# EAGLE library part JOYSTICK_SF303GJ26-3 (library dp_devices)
Multi way switch Mfr no: SF303GJ26-3 SF303GJ26-3
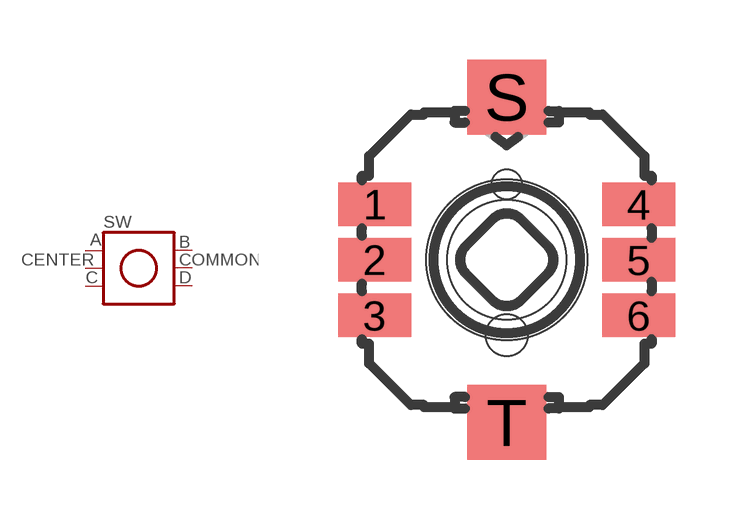
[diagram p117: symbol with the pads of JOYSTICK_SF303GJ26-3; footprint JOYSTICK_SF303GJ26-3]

Designator prefix SW

## JOYSTICK_SF303GJ26-3  [JOYSTICK_SF303GJ26-3]
1  A
2  CENTER
3  C
4  B
5  COMMON
6  D

## Footprint JOYSTICK_SF303GJ26-3 (pad centres in mm)
smd 1.85 x 1.1: 1 -3.325,1.4; 2 -3.325,0; 3 -3.325,-1.4; 4 3.325,1.4; 5 3.325,0; 6 3.325,-1.4
smd 2 x 1.9: S 0,4.1; T 0,-4.1
hole 0.75 at 0,1.9
hole 1.05 at 0,-1.9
